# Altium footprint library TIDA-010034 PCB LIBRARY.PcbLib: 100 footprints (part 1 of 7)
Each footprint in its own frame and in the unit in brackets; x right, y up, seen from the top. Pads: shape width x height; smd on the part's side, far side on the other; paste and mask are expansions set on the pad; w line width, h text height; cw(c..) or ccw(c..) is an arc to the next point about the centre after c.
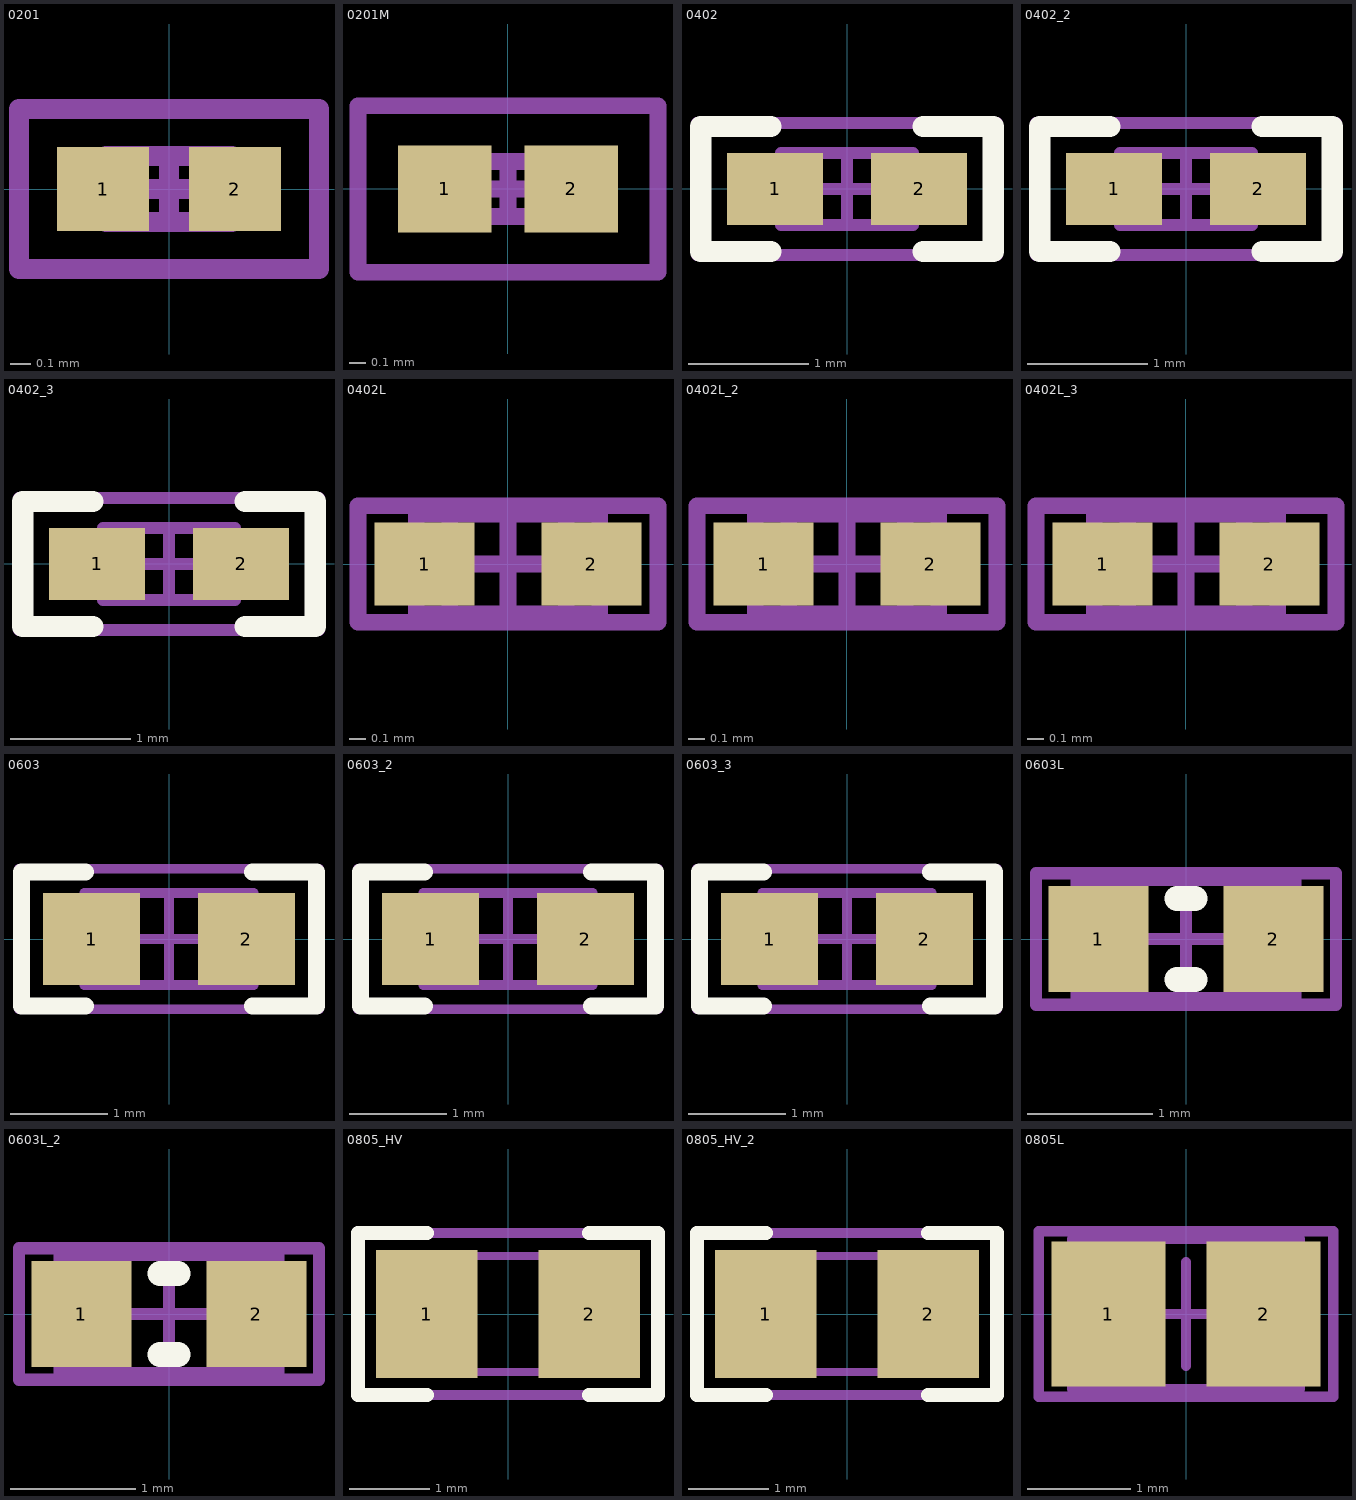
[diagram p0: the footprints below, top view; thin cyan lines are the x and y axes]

## 0201 [mm] "Data from Kemet datasheet CC101_COM dated 7/28/11"
height 0.26
pads (2):
  rect 0.46x0.42 smd mask+0.048: 1(-0.33,0) 2(0.33,0)
Mechanical 5:
  lines w0.1: -0.75,-0.4 -0.75,0.4 0.75,0.4 0.75,-0.4 -0.75,-0.4
  text ".Designator" at -0.66,-0.178 h0.36
Mechanical 13:
  lines w0.1: -0.215,-0.165 -0.215,0.165 ; 0.215,-0.165 0.215,0.165 ; -0.315,-0.165 0.315,-0.165 0.315,0.165 -0.315,0.165 -0.315,-0.165
Mechanical 15:
  lines w0.1: -0.165,0 0.165,0 ; 0,-0.165 0,0.165 ; -0.75,-0.4 0.75,-0.4 0.75,0.4 -0.75,0.4 -0.75,-0.4
3D body: height 0.26, standoff 0, extent 0.216,-0.164 0.314,0.164
3D body: height 0.26, standoff 0, extent -0.214,-0.164 0.214,0.164
3D body: height 0.26, standoff 0, extent -0.314,-0.164 -0.216,0.164

## 0201M [mm] "Data from Kemet datasheet CC101_COM dated 7/28/11"
height 0.26
pads (2):
  rect 0.56x0.52 smd mask+0.048: 1(-0.38,0) 2(0.38,0)
Mechanical 5:
  lines w0.1: -0.9,-0.5 0.9,-0.5 0.9,0.5 -0.9,0.5 -0.9,-0.5
  text ".Designator" at -0.725,-0.2 h0.38
Mechanical 13:
  lines w0.1: -0.215,-0.165 -0.215,0.165 ; 0.215,-0.165 0.215,0.165 ; -0.315,-0.165 -0.315,0.165 0.315,0.165 0.315,-0.165 -0.315,-0.165
Mechanical 15:
  lines w0.1: -0.165,0 0.165,0 ; 0,-0.165 0,0.165 ; -0.9,-0.5 -0.9,0.5 0.9,0.5 0.9,-0.5 -0.9,-0.5
3D body: height 0.26, standoff 0, extent -0.314,-0.164 -0.216,0.164
3D body: height 0.26, standoff 0, extent -0.214,-0.164 0.214,0.164
3D body: height 0.26, standoff 0, extent 0.216,-0.164 0.314,0.164

## 0402 [mm] "0402 from SM-752 data"
height 0.6
pads (2):
  rect 0.8x0.6 smd: 1(-0.6,0) 2(0.6,0)
Top Overlay:
  lines w0.178: -0.635,-0.521 -1.219,-0.521 -1.219,0.521 -0.635,0.521 ; 0.635,-0.521 1.219,-0.521 1.219,0.521 0.635,0.521
Mechanical 5:
  lines w0.1: -1.25,-0.55 1.25,-0.55 1.25,0.55 -1.25,0.55 -1.25,-0.55
  text ".Designator" at -1.117,-0.305 h0.61
Mechanical 13:
  lines w0.1: -0.35,-0.3 -0.35,0.3 ; 0.35,-0.3 0.35,0.3 ; -0.55,-0.3 -0.55,0.3 0.55,0.3 0.55,-0.3 -0.55,-0.3
Mechanical 15:
  lines w0.1: -0.3,0 0.3,0 ; 0,-0.3 0,0.3 ; -1.25,-0.55 -1.25,0.55 1.25,0.55 1.25,-0.55 -1.25,-0.55
3D body: height 0.6, standoff 0, extent -0.549,-0.299 -0.351,0.299
3D body: height 0.6, standoff 0, extent -0.349,-0.299 0.349,0.299
3D body: height 0.6, standoff 0, extent 0.351,-0.299 0.549,0.299

## 0402_2 [mm]
pads (2):
  rect 0.8x0.6 smd: 1(-0.6,0) 2(0.6,0)
Top Overlay:
  lines w0.178: -0.635,-0.521 -1.219,-0.521 -1.219,0.521 -0.635,0.521 ; 0.635,-0.521 1.219,-0.521 1.219,0.521 0.635,0.521
Mechanical 5:
  lines w0.1: -1.25,-0.55 1.25,-0.55 1.25,0.55 -1.25,0.55 -1.25,-0.55
  text ".Designator" at -1.117,-0.305 h0.61
Mechanical 13:
  lines w0.1: -0.35,-0.3 -0.35,0.3 ; 0.35,-0.3 0.35,0.3 ; -0.55,-0.3 -0.55,0.3 0.55,0.3 0.55,-0.3 -0.55,-0.3
Mechanical 15:
  lines w0.1: -0.3,0 0.3,0 ; 0,-0.3 0,0.3 ; -1.25,-0.55 -1.25,0.55 1.25,0.55 1.25,-0.55 -1.25,-0.55
3D body: height 0.6, standoff 0, extent -0.549,-0.299 -0.351,0.299
3D body: height 0.6, standoff 0, extent -0.349,-0.299 0.349,0.299
3D body: height 0.6, standoff 0, extent 0.351,-0.299 0.549,0.299

## 0402_3 [mm]
pads (2):
  rect 0.8x0.6 smd: 1(-0.6,0) 2(0.6,0)
Top Overlay:
  lines w0.178: -0.635,-0.521 -1.219,-0.521 -1.219,0.521 -0.635,0.521 ; 0.635,-0.521 1.219,-0.521 1.219,0.521 0.635,0.521
Mechanical 5:
  lines w0.1: -1.25,-0.55 1.25,-0.55 1.25,0.55 -1.25,0.55 -1.25,-0.55
  text ".Designator" at -1.117,-0.305 h0.61
Mechanical 13:
  lines w0.1: -0.35,-0.3 -0.35,0.3 ; 0.35,-0.3 0.35,0.3 ; -0.55,-0.3 -0.55,0.3 0.55,0.3 0.55,-0.3 -0.55,-0.3
Mechanical 15:
  lines w0.1: -0.3,0 0.3,0 ; 0,-0.3 0,0.3 ; -1.25,-0.55 -1.25,0.55 1.25,0.55 1.25,-0.55 -1.25,-0.55
3D body: height 0.6, standoff 0, extent -0.549,-0.299 -0.351,0.299
3D body: height 0.6, standoff 0, extent -0.349,-0.299 0.349,0.299
3D body: height 0.6, standoff 0, extent 0.351,-0.299 0.549,0.299

## 0402L [mm] "0402 from SM-752 data"
height 0.6
pads (2):
  rect 0.6x0.5 smd: 1(-0.5,0) 2(0.5,0)
Mechanical 5:
  lines w0.1: -0.9,-0.35 -0.9,0.35 0.9,0.35 0.9,-0.35 -0.9,-0.35
  text ".Designator" at -0.775,-0.225 h0.43
Mechanical 13:
  lines w0.1: -0.35,-0.3 -0.35,0.3 ; 0.35,-0.3 0.35,0.3 ; -0.55,-0.3 0.55,-0.3 0.55,0.3 -0.55,0.3 -0.55,-0.3
Mechanical 15:
  lines w0.1: -0.3,0 0.3,0 ; 0,-0.3 0,0.3 ; -0.9,-0.35 0.9,-0.35 0.9,0.35 -0.9,0.35 -0.9,-0.35
3D body: height 0.6, standoff 0, extent 0.351,-0.299 0.549,0.299
3D body: height 0.6, standoff 0, extent -0.349,-0.299 0.349,0.299
3D body: height 0.6, standoff 0, extent -0.549,-0.299 -0.351,0.299

## 0402L_2 [mm]
pads (2):
  rect 0.6x0.5 smd: 1(-0.5,0) 2(0.5,0)
Mechanical 5:
  lines w0.1: -0.9,-0.35 -0.9,0.35 0.9,0.35 0.9,-0.35 -0.9,-0.35
  text ".Designator" at -0.775,-0.225 h0.43
Mechanical 13:
  lines w0.1: -0.35,-0.3 -0.35,0.3 ; 0.35,-0.3 0.35,0.3 ; -0.55,-0.3 0.55,-0.3 0.55,0.3 -0.55,0.3 -0.55,-0.3
Mechanical 15:
  lines w0.1: -0.3,0 0.3,0 ; 0,-0.3 0,0.3 ; -0.9,-0.35 0.9,-0.35 0.9,0.35 -0.9,0.35 -0.9,-0.35
3D body: height 0.6, standoff 0, extent 0.351,-0.299 0.549,0.299
3D body: height 0.6, standoff 0, extent -0.349,-0.299 0.349,0.299
3D body: height 0.6, standoff 0, extent -0.549,-0.299 -0.351,0.299

## 0402L_3 [mm]
pads (2):
  rect 0.6x0.5 smd: 1(-0.5,0) 2(0.5,0)
Mechanical 5:
  lines w0.1: -0.9,-0.35 0.9,-0.35 0.9,0.35 -0.9,0.35 -0.9,-0.35
  text ".Designator" at -0.775,-0.225 h0.43
Mechanical 13:
  lines w0.1: -0.35,-0.3 -0.35,0.3 ; 0.35,-0.3 0.35,0.3 ; -0.55,-0.3 -0.55,0.3 0.55,0.3 0.55,-0.3 -0.55,-0.3
Mechanical 15:
  lines w0.1: -0.3,0 0.3,0 ; 0,-0.3 0,0.3 ; -0.9,-0.35 -0.9,0.35 0.9,0.35 0.9,-0.35 -0.9,-0.35
3D body: height 0.6, standoff 0, extent -0.549,-0.299 -0.351,0.299
3D body: height 0.6, standoff 0, extent -0.349,-0.299 0.349,0.299
3D body: height 0.6, standoff 0, extent 0.351,-0.299 0.549,0.299

## 0603 [mm] "0603 from SM-752 data"
height 1
pads (2):
  rect 1x0.95 smd: 1(-0.8,0) 2(0.8,0)
Top Overlay:
  lines w0.178: -0.864,-0.691 -1.524,-0.691 -1.524,0.693 -0.864,0.693 ; 0.864,-0.691 1.524,-0.691 1.524,0.693 0.864,0.693
Mechanical 5:
  lines w0.1: -1.55,-0.725 1.55,-0.725 1.55,0.725 -1.55,0.725 -1.55,-0.725
  text ".Designator" at -1.397,-0.381 h0.76
Mechanical 13:
  lines w0.1: -0.55,-0.475 -0.55,0.475 ; 0.55,-0.475 0.55,0.475 ; -0.875,-0.475 -0.875,0.475 0.875,0.475 0.875,-0.475 -0.875,-0.475
Mechanical 15:
  lines w0.1: -0.475,0 0.475,0 ; 0,-0.475 0,0.475 ; -1.55,-0.725 -1.55,0.725 1.55,0.725 1.55,-0.725 -1.55,-0.725
3D body: height 1, standoff 0, extent 0.551,-0.474 0.874,0.474
3D body: height 1, standoff 0, extent -0.549,-0.474 0.549,0.474
3D body: height 1, standoff 0, extent -0.874,-0.474 -0.551,0.474

## 0603_2 [mm]
pads (2):
  rect 1x0.95 smd: 1(-0.8,0) 2(0.8,0)
Top Overlay:
  lines w0.178: -0.864,-0.691 -1.524,-0.691 -1.524,0.693 -0.864,0.693 ; 0.864,-0.691 1.524,-0.691 1.524,0.693 0.864,0.693
Mechanical 5:
  lines w0.1: -1.55,-0.725 1.55,-0.725 1.55,0.725 -1.55,0.725 -1.55,-0.725
  text ".Designator" at -1.397,-0.381 h0.76
Mechanical 13:
  lines w0.1: -0.55,-0.475 -0.55,0.475 ; 0.55,-0.475 0.55,0.475 ; -0.875,-0.475 -0.875,0.475 0.875,0.475 0.875,-0.475 -0.875,-0.475
Mechanical 15:
  lines w0.1: -0.475,0 0.475,0 ; 0,-0.475 0,0.475 ; -1.55,-0.725 -1.55,0.725 1.55,0.725 1.55,-0.725 -1.55,-0.725
3D body: height 1, standoff 0, extent 0.551,-0.474 0.874,0.474
3D body: height 1, standoff 0, extent -0.549,-0.474 0.549,0.474
3D body: height 1, standoff 0, extent -0.874,-0.474 -0.551,0.474

## 0603_3 [mm]
pads (2):
  rect 1x0.95 smd: 1(-0.8,0) 2(0.8,0)
Top Overlay:
  lines w0.178: -0.864,-0.691 -1.524,-0.691 -1.524,0.693 -0.864,0.693 ; 0.864,-0.691 1.524,-0.691 1.524,0.693 0.864,0.693
Mechanical 5:
  lines w0.1: -1.55,-0.725 1.55,-0.725 1.55,0.725 -1.55,0.725 -1.55,-0.725
  text ".Designator" at -1.397,-0.381 h0.76
Mechanical 13:
  lines w0.1: -0.55,-0.475 -0.55,0.475 ; 0.55,-0.475 0.55,0.475 ; -0.875,-0.475 -0.875,0.475 0.875,0.475 0.875,-0.475 -0.875,-0.475
Mechanical 15:
  lines w0.1: -0.475,0 0.475,0 ; 0,-0.475 0,0.475 ; -1.55,-0.725 -1.55,0.725 1.55,0.725 1.55,-0.725 -1.55,-0.725
3D body: height 1, standoff 0, extent 0.551,-0.474 0.874,0.474
3D body: height 1, standoff 0, extent -0.549,-0.474 0.549,0.474
3D body: height 1, standoff 0, extent -0.874,-0.474 -0.551,0.474

## 0603L [mm] "0603 from SM-752 data"
height 1
pads (2):
  rect 0.8x0.85 smd: 1(-0.7,0) 2(0.7,0)
Top Overlay:
  lines w0.2: -0.071,-0.325 0.071,-0.325 ; -0.071,0.325 0.071,0.325
Mechanical 5:
  lines w0.1: -1.2,-0.525 1.2,-0.525 1.2,0.525 -1.2,0.525 -1.2,-0.525
  text ".Designator" at -1.05,-0.275 h0.56
Mechanical 13:
  lines w0.1: -0.55,-0.475 -0.55,0.475 ; 0.55,-0.475 0.55,0.475 ; -0.875,-0.475 0.875,-0.475 0.875,0.475 -0.875,0.475 -0.875,-0.475
Mechanical 15:
  lines w0.1: -0.475,0 0.475,0 ; 0,-0.475 0,0.475 ; -1.2,-0.525 -1.2,0.525 1.2,0.525 1.2,-0.525 -1.2,-0.525
3D body: height 1, standoff 0, extent -0.874,-0.474 -0.551,0.474
3D body: height 1, standoff 0, extent -0.549,-0.474 0.549,0.474
3D body: height 1, standoff 0, extent 0.551,-0.474 0.874,0.474

## 0603L_2 [mm]
pads (2):
  rect 0.8x0.85 smd: 1(-0.7,0) 2(0.7,0)
Top Overlay:
  lines w0.2: -0.071,-0.325 0.071,-0.325 ; -0.071,0.325 0.071,0.325
Mechanical 5:
  lines w0.1: -1.2,-0.525 1.2,-0.525 1.2,0.525 -1.2,0.525 -1.2,-0.525
  text ".Designator" at -1.05,-0.275 h0.56
Mechanical 13:
  lines w0.1: -0.55,-0.475 -0.55,0.475 ; 0.55,-0.475 0.55,0.475 ; -0.875,-0.475 0.875,-0.475 0.875,0.475 -0.875,0.475 -0.875,-0.475
Mechanical 15:
  lines w0.1: -0.475,0 0.475,0 ; 0,-0.475 0,0.475 ; -1.2,-0.525 -1.2,0.525 1.2,0.525 1.2,-0.525 -1.2,-0.525
3D body: height 1, standoff 0, extent -0.874,-0.474 -0.551,0.474
3D body: height 1, standoff 0, extent -0.549,-0.474 0.549,0.474
3D body: height 1, standoff 0, extent 0.551,-0.474 0.874,0.474

## 0805_HV [mil] "0805 with 30mil clearance between pads"
height 57.09
pads (2):
  rect 50x63 smd: 1(-40,0) 2(40,0)
Top Overlay:
  lines w7: -40,-40 -74,-40 -74,0 -74,40 -40,40 ; 40,-40 74,-40 74,0 74,40 40,40
Mechanical 5:
  lines w5: -74,-40 74,-40 74,40 -74,40 -74,-40
  text ".Designator" at -64,-17 h35
Mechanical 13:
  lines w3.94: -25.59,-28.54 -25.59,28.54 ; 25.59,-28.54 25.59,28.54 ; -43.31,-28.54 43.31,-28.54 43.31,28.54 -43.31,28.54 -43.31,-28.54
3D body: height 57.09, standoff 0, extent -43.29,-28.52 -25.61,28.52
3D body: height 57.09, standoff 0, extent -25.57,-28.52 25.57,28.52
3D body: height 57.09, standoff 0, extent 25.61,-28.52 43.29,28.52

## 0805_HV_2 [mil]
pads (2):
  rect 50x63 smd: 1(-40,0) 2(40,0)
Top Overlay:
  lines w7: -40,-40 -74,-40 -74,0 -74,40 -40,40 ; 40,-40 74,-40 74,0 74,40 40,40
Mechanical 5:
  lines w5: -74,-40 74,-40 74,40 -74,40 -74,-40
  text ".Designator" at -64,-17 h35
Mechanical 13:
  lines w3.94: -25.59,-28.54 -25.59,28.54 ; 25.59,-28.54 25.59,28.54 ; -43.31,-28.54 43.31,-28.54 43.31,28.54 -43.31,28.54 -43.31,-28.54
3D body: height 57.09, standoff 0, extent -43.29,-28.52 -25.61,28.52
3D body: height 57.09, standoff 0, extent -25.57,-28.52 25.57,28.52
3D body: height 57.09, standoff 0, extent 25.61,-28.52 43.29,28.52

## 0805L [mm] "0805 from SM-752 data"
height 1.45
pads (2):
  rect 1.1x1.4 smd: 1(-0.75,0) 2(0.75,0)
Mechanical 5:
  lines w0.1: -1.425,-0.8 -1.425,0.8 1.425,0.8 1.425,-0.8 -1.425,-0.8
  text ".Designator" at -1.2,-0.325 h0.64
Mechanical 13:
  lines w0.1: -0.65,-0.725 -0.65,0.725 ; 0.65,-0.725 0.65,0.725 ; -1.1,-0.725 1.1,-0.725 1.1,0.725 -1.1,0.725 -1.1,-0.725
Mechanical 15:
  lines w0.1: -0.5,0 0.5,0 ; 0,-0.5 0,0.5 ; -1.425,-0.8 1.425,-0.8 1.425,0.8 -1.425,0.8 -1.425,-0.8
3D body: height 1.45, standoff 0, extent -1.099,-0.724 -0.651,0.724
3D body: height 1.45, standoff 0, extent -0.649,-0.724 0.649,0.724
3D body: height 1.45, standoff 0, extent 0.651,-0.724 1.099,0.724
